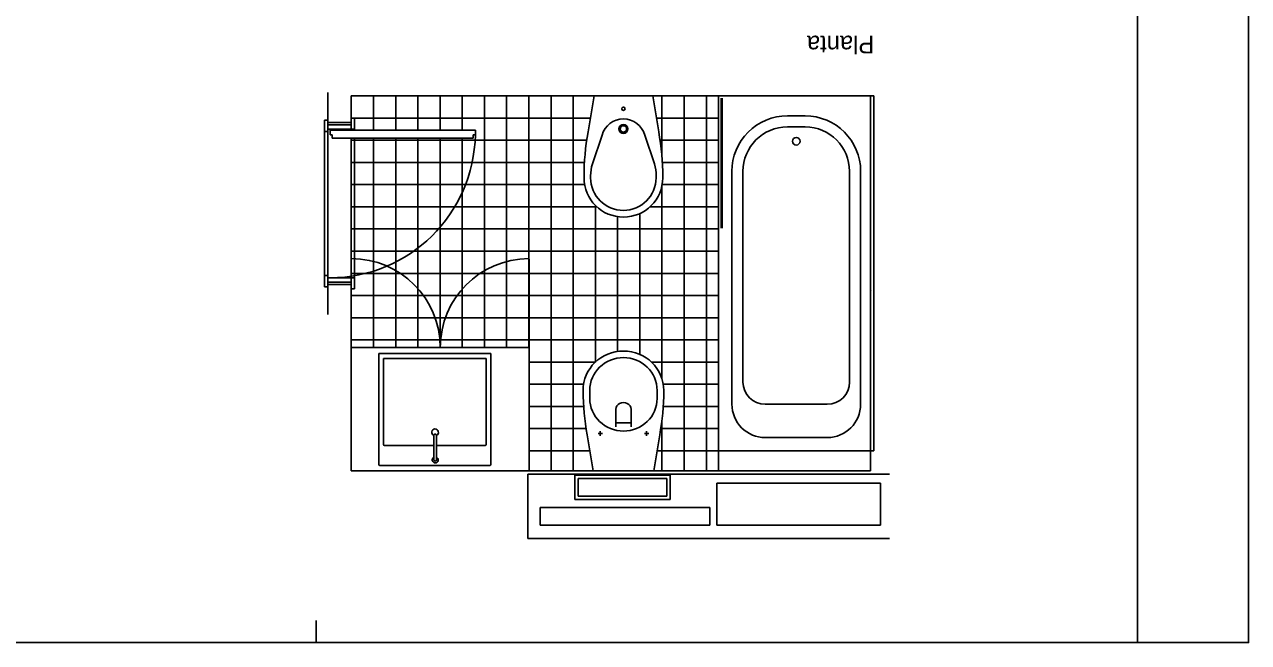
# Model space of a CAD drawing. Extents: x 1295.6 to 1307.2, y -291.8 to -285.9.
# Drawn here: x 1301.67 to 1307.18, y -291.84 to -289.06 of the extents above; entities that cross this region are included whole.
import ezdxf

# ---------------------------------------------------------------- set-up
doc = ezdxf.new("R2010")
doc.units = 0
for name, color, linetype in [('Level 1', 7, 'Continuous'), ('Level 10', 7, 'Continuous'), ('Level 11', 7, 'Continuous'), ('Level 13', 7, 'Continuous'), ('Level 2', 7, 'Continuous'), ('Level 36', 7, 'Continuous'), ('Level 4', 7, 'Continuous'), ('Level 60', 7, 'Continuous'), ('Level 62', 7, 'Continuous')]:
    doc.layers.add(name, color=color, linetype=linetype)

msp = doc.modelspace()

# ---------------------------------------------------------------- linework, layer by layer
at = {"layer": 'Level 1'}
for p, q in [((1303.0357, -289.3644), (1303.0357, -289.4994)), ((1303.1407, -289.3794), (1305.4807, -289.3794)), ((1303.1407, -289.3794), (1303.1407, -289.4994)), ((1305.4807, -289.3794), (1305.4807, -291.0694)), ((1303.1407, -289.4994), (1303.0357, -289.4994)), ((1303.0357, -290.2294), (1303.0357, -290.3644)), ((1303.1407, -290.2294), (1303.0357, -290.2294)), ((1303.0457, -290.2294), (1303.0357, -290.2294)), ((1303.1407, -290.2294), (1303.1307, -290.2294)), ((1303.1407, -291.0694), (1303.1407, -290.2294)), ((1303.1407, -291.0694), (1305.4807, -291.0694)), ((1303.9361, -291.0844), (1303.9361, -291.3744)), ((1303.9361, -291.0844), (1305.5657, -291.0844)), ((1304.7878, -291.1244), (1304.7878, -291.3144)), ((1304.7878, -291.1244), (1305.5257, -291.1244)), ((1305.5257, -291.1244), (1305.5257, -291.3144)), ((1303.9911, -291.2344), (1303.9911, -291.3144)), ((1304.7557, -291.2344), (1303.9911, -291.2344)), ((1304.7557, -291.3144), (1304.7557, -291.2344)), ((1303.9911, -291.3144), (1304.7557, -291.3144)), ((1304.7878, -291.3144), (1305.5257, -291.3144)), ((1303.9361, -291.3744), (1305.5657, -291.3744))]:
    msp.add_line(p, q, dxfattribs=at)
at = {"layer": 'Level 10'}
for p, q in [((1303.2407, -289.5344), (1303.2407, -289.3794)), ((1303.3407, -289.5344), (1303.3407, -289.3794)), ((1303.4407, -289.5344), (1303.4407, -289.3794)), ((1303.5407, -289.5344), (1303.5407, -289.3794)), ((1303.6407, -289.5344), (1303.6407, -289.3794)), ((1303.7407, -290.5139), (1303.7407, -289.3794)), ((1303.8407, -290.5139), (1303.8407, -289.3794)), ((1303.9407, -290.5139), (1303.9407, -289.3794)), ((1304.0407, -291.0694), (1304.0407, -289.3794)), ((1304.1407, -291.0694), (1304.1407, -289.3794)), ((1304.5407, -289.6552), (1304.5407, -289.3794)), ((1304.6407, -291.0694), (1304.6407, -289.3794)), ((1304.7407, -291.0694), (1304.7407, -289.3794)), ((1303.1557, -289.4794), (1304.2181, -289.4794)), ((1304.5156, -289.4794), (1304.7957, -289.4794)), ((1303.0357, -290.1894), (1303.0357, -289.5394)), ((1303.1407, -290.1994), (1303.1407, -289.5694)), ((1303.1407, -289.5794), (1304.2016, -289.5794)), ((1303.2407, -290.5139), (1303.2407, -289.5694)), ((1303.3407, -290.5139), (1303.3407, -289.5694)), ((1303.4407, -290.5139), (1303.4407, -289.5694)), ((1303.5407, -290.5139), (1303.5407, -289.5694)), ((1303.6407, -290.5139), (1303.6407, -289.5694)), ((1304.5321, -289.5794), (1304.7957, -289.5794)), ((1303.1407, -289.6794), (1304.1912, -289.6794)), ((1304.5424, -289.6794), (1304.7957, -289.6794)), ((1303.1407, -289.7794), (1304.1921, -289.7794)), ((1304.5407, -290.6542), (1304.5407, -289.7838)), ((1304.5416, -289.7794), (1304.7957, -289.7794)), ((1303.1407, -289.8794), (1304.2472, -289.8794)), ((1304.2407, -290.5792), (1304.2407, -289.8732)), ((1304.4864, -289.8794), (1304.7957, -289.8794)), ((1304.3407, -290.5312), (1304.3407, -289.9238)), ((1304.4407, -290.5445), (1304.4407, -289.9096)), ((1303.1407, -289.9794), (1304.7957, -289.9794)), ((1303.1407, -290.0794), (1304.7957, -290.0794)), ((1303.1407, -290.1794), (1304.7957, -290.1794)), ((1303.1407, -290.2794), (1304.7957, -290.2794)), ((1303.1407, -290.3794), (1304.7957, -290.3794)), ((1303.1407, -290.4794), (1304.7957, -290.4794)), ((1303.9427, -290.5794), (1304.2405, -290.5794)), ((1304.4937, -290.5794), (1304.7957, -290.5794)), ((1303.9427, -290.6794), (1304.1874, -290.6794)), ((1304.5467, -290.6794), (1304.7957, -290.6794)), ((1303.9427, -290.7794), (1304.1874, -290.7794)), ((1304.5485, -290.7794), (1304.7957, -290.7794)), ((1304.5407, -291.0694), (1304.5407, -290.8414)), ((1303.9427, -290.8794), (1304.1989, -290.8794)), ((1304.5353, -290.8794), (1304.7957, -290.8794)), ((1303.9427, -290.9794), (1304.2156, -290.9794)), ((1304.5185, -290.9794), (1304.7957, -290.9794))]:
    msp.add_line(p, q, dxfattribs=at)
at = {"layer": 'Level 11'}
for p, q in [((1304.2345, -289.3795), (1304.2079, -289.5416)), ((1304.2345, -289.3795), (1304.4992, -289.3795)), ((1304.4992, -289.3795), (1304.5258, -289.5416)), ((1305.4957, -289.3794), (1304.7957, -289.3794)), ((1304.7957, -289.3794), (1304.7957, -290.9794)), ((1305.4957, -289.3794), (1305.4957, -290.9794)), ((1305.1857, -289.4694), (1305.1057, -289.4694)), ((1305.1857, -289.5194), (1305.1057, -289.5194)), ((1304.227, -289.6853), (1304.2707, -289.5561)), ((1304.5067, -289.6853), (1304.463, -289.5561)), ((1304.8557, -289.7194), (1304.8557, -290.7694)), ((1304.9057, -289.7194), (1304.9057, -290.6694)), ((1305.3857, -289.7194), (1305.3857, -290.6694)), ((1305.4357, -289.7194), (1305.4357, -290.7694)), ((1304.1893, -289.7449), (1304.1893, -289.7486)), ((1304.2193, -289.7483), (1304.2193, -289.7402)), ((1304.5143, -289.7483), (1304.5143, -289.7402)), ((1304.5443, -289.7449), (1304.5443, -289.7486)), ((1303.2645, -290.5413), (1303.2645, -291.0405)), ((1303.7689, -290.5413), (1303.2645, -290.5413)), ((1303.7689, -291.0405), (1303.7689, -290.5413)), ((1303.2856, -290.9509), (1303.2856, -290.5624)), ((1303.7478, -290.5624), (1303.2856, -290.5624)), ((1303.7478, -290.9509), (1303.7478, -290.5624)), ((1304.1852, -290.7102), (1304.1852, -290.7065)), ((1304.2152, -290.7068), (1304.2152, -290.7429)), ((1304.5189, -290.7068), (1304.5189, -290.7429)), ((1304.5489, -290.7102), (1304.5489, -290.7065)), ((1304.3327, -290.8714), (1304.3327, -290.7917)), ((1304.4014, -290.8714), (1304.4014, -290.7916)), ((1305.2857, -290.7694), (1305.0057, -290.7694)), ((1304.3327, -290.8537), (1304.4014, -290.8537)), ((1303.5128, -291.0197), (1303.5128, -290.9102)), ((1303.5241, -291.0197), (1303.5241, -290.9102)), ((1304.2304, -291.0694), (1304.2038, -290.9074)), ((1304.2527, -290.9012), (1304.2727, -290.9012)), ((1304.2627, -290.9112), (1304.2627, -290.8912)), ((1304.4614, -290.9012), (1304.4814, -290.9012)), ((1304.4714, -290.9112), (1304.4714, -290.8912)), ((1304.5037, -291.0694), (1304.5303, -290.9074)), ((1305.2857, -290.9194), (1305.0057, -290.9194)), ((1303.29, -290.9553), (1303.5128, -290.9553)), ((1303.5241, -290.9553), (1303.7435, -290.9553)), ((1305.4957, -290.9794), (1304.7957, -290.9794)), ((1303.2689, -291.0449), (1303.7645, -291.0449)), ((1304.1477, -291.0894), (1304.1477, -291.1994)), ((1304.5777, -291.0894), (1304.1477, -291.0894)), ((1304.2304, -291.0694), (1304.5037, -291.0694)), ((1304.5777, -291.0894), (1304.5777, -291.1994)), ((1304.5627, -291.1044), (1304.1627, -291.1044)), ((1304.1627, -291.1044), (1304.1627, -291.1844)), ((1304.5627, -291.1044), (1304.5627, -291.1844)), ((1304.5777, -291.1994), (1304.1477, -291.1994)), ((1304.5627, -291.1844), (1304.1627, -291.1844))]:
    msp.add_line(p, q, dxfattribs=at)
for centre, radius in [((1304.3668, -289.4375), 0.00766), ((1304.3668, -289.5284), 0.02), ((1304.3668, -289.5284), 0.0146), ((1305.1457, -289.5838), 0.0173)]:
    msp.add_circle(centre, radius, dxfattribs=at)
for centre, radius, start, end in [((1304.3668, -289.5835), 0.1, 15.9317, 164.1953), ((1305.1057, -289.7194), 0.25, 89.9999, 180), ((1305.1857, -289.7194), 0.25, 0.0001, 90.0001), ((1305.1057, -289.7194), 0.2, 90, 180), ((1305.1857, -289.7194), 0.2, 360, 90), ((1304.4193, -289.7402), 0.2, 164.0693, 180.0006), ((1304.3143, -289.7402), 0.2, 0.0017, 15.9319), ((1304.3668, -289.7483), 0.1775, 180.0002, 359.9999), ((1304.3668, -289.7483), 0.1475, 180.0002, 359.9999), ((1305.0057, -290.6694), 0.1, 180.0001, 269.9999), ((1305.2857, -290.6694), 0.1, 270, 0), ((1305.0057, -290.7694), 0.15, 179.9998, 270.0001), ((1305.2857, -290.7694), 0.15, 270, 0), ((1303.5181, -290.8958), 0.015, 293.6307, 249.2833), ((1303.5184, -290.9096), 0.00566, 354.0176, 185.9962), ((1303.29, -290.9509), 0.00438, 180, 270), ((1303.7435, -290.9509), 0.00438, 270, 0), ((1303.2689, -291.0405), 0.00438, 180, 270), ((1303.5189, -291.0203), 0.0135, 116.7199, 67.3909), ((1303.5184, -291.0203), 0.00566, 174.0038, 5.9824), ((1303.7645, -291.0405), 0.00438, 270, 0)]:
    msp.add_arc(centre, radius, start, end, dxfattribs=at)
for centre, major_axis, ratio, start_param, end_param in [((1305.5893, -289.7449), (-1.4, 0), 0.895428, 6.120269, 6.283187), ((1303.1443, -289.7449), (1.4, 0), 0.895428, 6.283183, 6.446102), ((1304.3671, -290.7068), (0.1818, 0), 0.976148, 0.000002, 3.141589), ((1304.3671, -290.7068), (0.1518, 0), 0.971435, 0.000002, 3.141589), ((1305.5847, -290.7102), (-1.3994, 0), 0.868644, 6.283183, 6.446101), ((1303.1483, -290.7102), (1.4006, 0), 0.867922, 6.120268, 6.283186), ((1304.3671, -290.7429), (0.1518, 0), 0.971435, 3.141595, 6.283182), ((1304.3671, -290.7918), (0.0343, 0), 0.873689, 6.283163, 9.424786)]:
    msp.add_ellipse(centre, major_axis=major_axis, ratio=ratio, start_param=start_param, end_param=end_param, dxfattribs=at)
at = {"layer": 'Level 13'}
for p, q in [((1303.0207, -289.4894), (1303.0207, -289.5394)), ((1303.0357, -289.4894), (1303.0207, -289.4894)), ((1303.0357, -289.5394), (1303.0357, -289.4894)), ((1303.1407, -289.5294), (1303.1407, -289.4794)), ((1303.1407, -289.4794), (1303.1557, -289.4794)), ((1303.1557, -289.4794), (1303.1557, -289.5294)), ((1303.0207, -289.5394), (1303.0357, -289.5394)), ((1303.1407, -289.5094), (1303.0357, -289.5094)), ((1303.0357, -289.5094), (1303.0357, -289.5394)), ((1303.0357, -289.5294), (1303.1407, -289.5294)), ((1303.7001, -289.5344), (1303.0451, -289.5344)), ((1303.0451, -289.5344), (1303.0451, -289.5544)), ((1303.0451, -289.5544), (1303.0551, -289.5544)), ((1303.0551, -289.5544), (1303.0551, -289.5694)), ((1303.1407, -289.5294), (1303.1407, -289.5094)), ((1303.1557, -289.5294), (1303.1407, -289.5294)), ((1303.6901, -289.5544), (1303.6998, -289.5544)), ((1303.6901, -289.5694), (1303.6901, -289.5544)), ((1303.7001, -289.5544), (1303.7001, -289.5344)), ((1303.0551, -289.5694), (1303.6901, -289.5694)), ((1303.0207, -290.2394), (1303.0207, -290.1894)), ((1303.0207, -290.1894), (1303.0357, -290.1894)), ((1303.0357, -290.2194), (1303.0357, -290.1894)), ((1303.0357, -290.1894), (1303.0357, -290.2394)), ((1303.0357, -290.1994), (1303.1407, -290.1994)), ((1303.1407, -290.1994), (1303.1407, -290.2194)), ((1303.1557, -290.1994), (1303.1407, -290.1994)), ((1303.1407, -290.1994), (1303.1407, -290.2494)), ((1303.1557, -290.2494), (1303.1557, -290.1994)), ((1303.0357, -290.2394), (1303.0207, -290.2394)), ((1303.1407, -290.2194), (1303.0357, -290.2194)), ((1303.1407, -290.2494), (1303.1557, -290.2494))]:
    msp.add_line(p, q, dxfattribs=at)
at = {"layer": 'Level 2'}
for p, q in [((1303.1407, -290.5139), (1303.9427, -290.5139)), ((1303.1407, -291.0694), (1303.1407, -290.5139)), ((1303.9427, -290.5139), (1303.9427, -291.0694)), ((1304.7957, -290.9794), (1304.7957, -291.0694))]:
    msp.add_line(p, q, dxfattribs=at)
at = {"layer": 'Level 36'}
for p, q in [((1304.8072, -289.9761), (1304.8072, -289.3894)), ((1304.8122, -289.9761), (1304.8122, -289.3894)), ((1304.8072, -289.9661), (1304.8122, -289.9661))]:
    msp.add_line(p, q, dxfattribs=at)
at = {"layer": 'Level 4'}
for p, q in [((1303.0207, -289.5394), (1303.0207, -290.1894)), ((1303.1557, -290.1994), (1303.1557, -289.5694)), ((1303.9427, -290.5139), (1303.9427, -290.1151))]:
    msp.add_line(p, q, dxfattribs=at)
for centre, start, end in [((1303.1407, -290.5139), 0, 90), ((1303.9427, -290.5139), 90.2861, 180)]:
    msp.add_arc(centre, 0.401, start, end, dxfattribs=at)
msp.add_ellipse((1303.045, -289.5408), major_axis=(0, 0.6586), ratio=0.994272, start_param=3.141593, end_param=4.691673, dxfattribs=at)
at = {"layer": 'Level 62'}
for p, q in [((1306.6835, -291.8434), (1306.6835, -285.9034)), ((1305.4857, -290.2544), (1305.4857, -290.2544)), ((1302.9831, -291.7434), (1302.9831, -291.8434)), ((1306.6835, -291.8434), (1307.1835, -291.8434))]:
    msp.add_line(p, q, dxfattribs=at)
msp.add_lwpolyline([(1307.1835, -285.9034), (1307.1835, -291.8434), (1295.5839, -291.8434), (1295.5839, -285.9034)], close=True, dxfattribs=at)

# ---------------------------------------------------------------- texts
at = {"layer": 'Level 60'}
msp.add_text('Planta', height=0.08, rotation=180, dxfattribs=at).set_placement((1305.4969, -289.1081))

doc.saveas('drawing.dxf')
